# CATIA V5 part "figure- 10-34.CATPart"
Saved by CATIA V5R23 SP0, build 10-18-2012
Part number: Part1
Bounding box of the stored display mesh (mm): x -20 to 20, y -0.339 to 152.641, z -44.55 to 10.195
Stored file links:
  D:\APS\CATIA V5-6R-2013-Project\CATIA V5-6R2013_partfiles\Part_Files\c10_catia_v5-6r2013_prt\figure- 10-34.CATPart
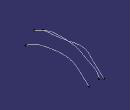
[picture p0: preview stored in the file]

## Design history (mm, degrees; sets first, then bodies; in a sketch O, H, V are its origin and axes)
Set1
  Plane1: type Offset, RefPlane yz-plane, Offset 20, reversed
  Sketch1 on yz-plane, origin (0, 0, 0), H (0, 1, 0), V (0, 0, 1)
    spline S1 through (-0.3393, -8.9363) (20.4957, 1.6782) (43.9804, 9.0119) (85.9797, 8.8277) (110.0875, 1.9736) (113.4186, 0.0053) (148.283, -20.6228) (152.6411, -30.7916)
  Sketch2 on Plane1, origin (-20, 0, 0), H (0, 1, 0), V (0, 0, 1)
    spline S1 through (0, -18.2863) (39.7074, -13.5111) (76.5446, -6.6894) (104.5136, -9.077) (112.3585, -15.8987) (129.7538, -32.6118) (143.3972, -44.5498)
  Plane2: type Offset, RefPlane yz-plane, Offset 20
  Sketch3 on Plane2, origin (20, 0, 0), H (0, 1, 0), V (0, 0, 1)
    spline S1 through (0, -29.0463) (25.3574, -14.3797) (67.652, -5.1704) (115.4039, -10.2866) (140.3031, -31.4339) (148.4891, -38.2556)
Body1 (main body)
